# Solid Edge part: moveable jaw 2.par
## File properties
Author: CADSoft
Template: Normal.par
Last saved by: CADCIM
Revision: 4
Application: Solid Edge
Accuracy: 0.990
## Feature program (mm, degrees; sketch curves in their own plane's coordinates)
sketch for "unnamed Protrusion 1" plane through (0, 0, 0) normal (0, -1, 0) x-axis (1, 0, 0)
  line (2.077, -7.5) -> (2.077, 52.5)
  line (2.077, 52.5) -> (-32.423, 52.5)
  line (-32.423, 52.5) -> (-32.423, -7.5)
  line (-28.923, -7.5) -> (-32.423, -7.5)
  line (-28.923, -5) -> (-28.923, -7.5)
  line (-28.923, -5) -> (-26.423, -5)
  line (-26.423, -5) -> (-26.423, -2.5)
  line (-26.423, -2.5) -> (-23.923, -2.5)
  line (-23.923, -2.5) -> (-23.923, 0)
  line (-23.923, 0) -> (-21.423, 0)
  line (-21.423, 0) -> (-21.423, 2.5)
  line (-21.423, 2.5) -> (-18.923, 2.5)
  line (-18.923, 2.5) -> (-18.923, 5)
  line (-18.923, 5) -> (-16.423, 5)
  line (-16.423, 5) -> (-16.423, 7.5)
  line (-16.423, 7.5) -> (-15.173, 7.5)
  line (-13.923, 7.5) -> (-15.173, 7.5)
  line (-13.923, 5) -> (-13.923, 7.5)
  line (-11.423, 5) -> (-13.923, 5)
  line (-11.423, 2.5) -> (-11.423, 5)
  line (-8.923, 2.5) -> (-11.423, 2.5)
  line (-8.923, 0) -> (-8.923, 2.5)
  line (-6.423, 0) -> (-8.923, 0)
  line (-6.423, -2.5) -> (-6.423, 0)
  line (-3.923, -2.5) -> (-6.423, -2.5)
  line (-3.923, -5) -> (-3.923, -2.5)
  line (-1.423, -5) -> (-3.923, -5)
  line (-1.423, -5) -> (-1.423, -7.5)
  line (-1.423, -7.5) -> (2.077, -7.5)
extrude "unnamed Protrusion 1" add finite 18 symmetric
sketch for "Hole_1" plane through (-15.173, 0, 52.5) normal (0, 0, 1) x-axis (-1, 0, 0)
  hole centre (0, 0) bore radius 6
hole "Hole_1" diameter 12 finite  VBottomAngle = 120 deg
sketch for "Hole_2" plane through (2.077, 0, 22.5) normal (1, 0, 0) x-axis (0, 1, 0)
  hole centre (0, 23) bore radius 3
hole "Hole_2" diameter 6 through
chamfer "Chamfer_2" setback 2
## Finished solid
Body 1: solid body, 38 faces, 98 edges, 60 vertices.
  Faces by surface: plane 34, cylinder 3, cone 1
  Edges by curve: line 92, circle 4, intersection 2
Bounding box of the edges (mm): 34.500 x 18.000 x 60.000, from (-32.423, -9, -7.5) to (2.077, 9, 52.5).
Cylindrical faces by radius (mm): R3 x2, R6 x1
Conical faces (half-angle, radius in mm at the cone's reference point): 60 deg R6 x1
Planar faces by outward normal: +x 7, +y 1, +z 1, -x 7, -y 1, -z 13, oblique 4
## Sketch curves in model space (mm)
line (-26.423, 0, -5) -> (-26.423, 0, -2.5)
line (-26.423, 0, -2.5) -> (-23.923, 0, -2.5)
line (-23.923, 0, -2.5) -> (-23.923, 0, 0)
line (-23.923, 0, 0) -> (-21.423, 0, 0)
line (-21.423, 0, 0) -> (-21.423, 0, 2.5)
line (-21.423, 0, 2.5) -> (-18.923, 0, 2.5)
line (-18.923, 0, 2.5) -> (-18.923, 0, 5)
line (-18.923, 0, 5) -> (-16.423, 0, 5)
line (-16.423, 0, 5) -> (-16.423, 0, 7.5)
line (-16.423, 0, 7.5) -> (-15.173, 0, 7.5)
line (-13.923, 0, 7.5) -> (-15.173, 0, 7.5)
line (-13.923, 0, 5) -> (-13.923, 0, 7.5)
line (-11.423, 0, 5) -> (-13.923, 0, 5)
line (-11.423, 0, 2.5) -> (-11.423, 0, 5)
line (-8.923, 0, 2.5) -> (-11.423, 0, 2.5)
line (-8.923, 0, 0) -> (-8.923, 0, 2.5)
line (-6.423, 0, 0) -> (-8.923, 0, 0)
line (-6.423, 0, -2.5) -> (-6.423, 0, 0)
line (-3.923, 0, -2.5) -> (-6.423, 0, -2.5)
line (-3.923, 0, -5) -> (-3.923, 0, -2.5)
line (-1.423, 0, -5) -> (-3.923, 0, -5)
line (-1.423, 0, -5) -> (-1.423, 0, -7.5)
line (-1.423, 0, -7.5) -> (2.077, 0, -7.5)
line (2.077, 0, -7.5) -> (2.077, 0, 52.5)
line (2.077, 0, 52.5) -> (-32.423, 0, 52.5)
line (-32.423, 0, 52.5) -> (-32.423, 0, -7.5)
line (-28.923, 0, -7.5) -> (-32.423, 0, -7.5)
line (-28.923, 0, -5) -> (-28.923, 0, -7.5)
line (-28.923, 0, -5) -> (-26.423, 0, -5)
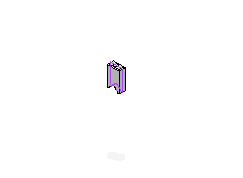
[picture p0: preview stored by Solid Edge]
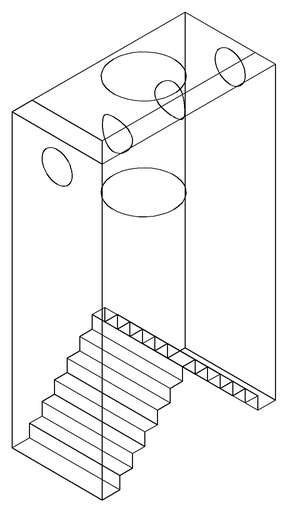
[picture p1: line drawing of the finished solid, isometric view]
